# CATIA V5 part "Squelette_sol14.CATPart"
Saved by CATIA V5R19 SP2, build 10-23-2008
Part number: Squelette_sol14
Bounding box of the stored display mesh (mm): x 0 to 30, y 0 to 0, z 0 to 192
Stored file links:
  G:\Documents\IFMA\COURS\2A\S3\CFAO\ProjetCFAO\Squelette_sol14.CATPart
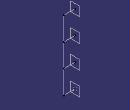
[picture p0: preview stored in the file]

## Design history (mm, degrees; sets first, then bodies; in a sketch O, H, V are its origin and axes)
Parameters
  Separationroue_sol14 = 64 mm
Set1
  Point1: (0, 0, 0)
  Line1: type PtDir, RefPoint Point1, Direction yz-plane, Start 0, End 30
  Line2: type PtDir, RefPoint vertex of Line1, Direction xy-plane, Start 0, End 64 {= Separationroue_sol14}
  Line3: type PtDir, RefPoint vertex of Line2, Direction Line2, Start 0, End 64 {= Separationroue_sol14}
  Line4: type PtDir, RefPoint vertex of Line3, Direction Line2, Start 0, End 64 {= Separationroue_sol14}
  Line5: type PtDir, RefPoint vertex of Line2, Direction Line1, Start 0, End -30
  Line6: type PtDir, RefPoint vertex of Line3, Direction Line1, Start 0, End -30
  Line7: type PtDir, RefPoint vertex of Line4, Direction Line1, Start 0, End -30
  Plane1: type Normal, Curve Line5, RefPoint vertex of Line5
  Plane2: type Normal, Curve Line6, RefPoint vertex of Line6
  Plane3: type Normal, Curve Line7, RefPoint vertex of Line7
Body1 (main body)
